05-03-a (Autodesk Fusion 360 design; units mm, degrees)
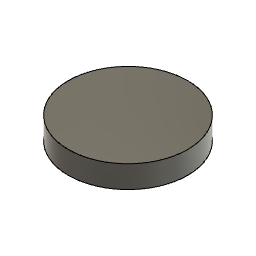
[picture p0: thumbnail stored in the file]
sketch "スケッチ1" plane through (0, 0, 0) normal (0, 0, 1) x axis (1, 0, 0)
  line L1 (-7, -2) -> (-8, -2)
  line L2 (-7, 0) -> (-7, -2)
  line L3 (-8, 0) -> (-7, 0)
  line L4 (-8, -2) -> (-8, 0)
  line L5 (0, 22.5) -> (0, 1.75)
  point P1 (0, 0)
  point P4 (-7, 0)
  point P2 (-8, -2)
  point P3 (-7, -2)
  point P5 (-8, 0)
  horizontal L1
  vertical L2
  horizontal L3
  vertical L4
  horizontal P1 P4
  dimension "d1" distance P2 P3 = 1
  dimension "d2" distance P2 P5 = 2
  dimension "d3" = 16
revolve "回転1" sketch "スケッチ1" AlongAngle 360
sketch "スケッチ2" plane through (0, 0, 0) normal (0, 0, 1) x axis (1, 0, 0)
  line L1 (-8, 0) -> (0, 0)
  line L2 (-8, 1) -> (-8, 0)
  line L3 (0, 1) -> (-8, 1)
  line L4 (0, 0) -> (0, 1)
  line L5 (-8, -2) -> (-8, 0)
  line L6 (8, 0) -> (8, -2)
  point P1 (0, 0)
  point P2 (0, 0)
  point P3 (-8, 0)
  point P4 (-8, 1)
  horizontal L1
  vertical L2
  horizontal L3
  vertical L4
  coincident P1 P2
  collinear L2 L5
  dimension "d5" distance P3 P4 = 1
revolve "回転2" sketch "スケッチ2" AlongAngle 360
